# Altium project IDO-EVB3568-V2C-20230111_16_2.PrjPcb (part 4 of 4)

## Sheet P20.SchDoc
size 297 x 209 mm
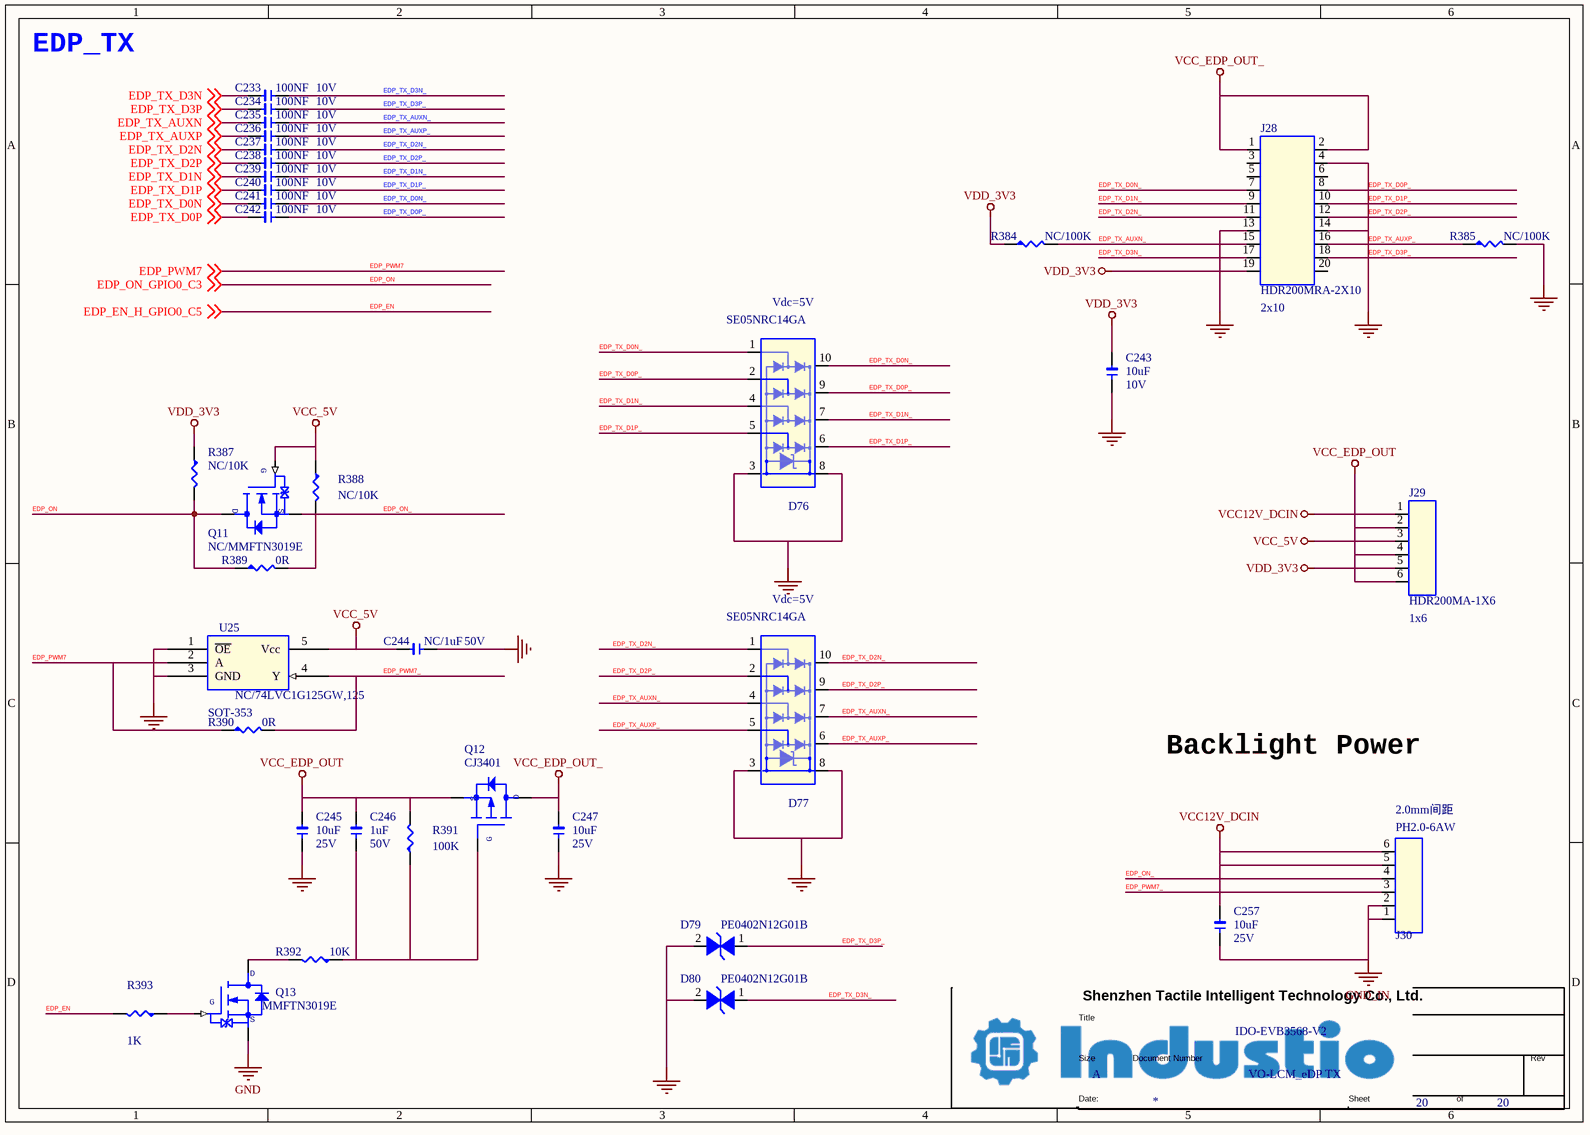
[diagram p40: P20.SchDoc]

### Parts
(Parts that share a designator on the sheet are numbered #1, #2 ... from top to bottom, then left to right.)
*#19  Doc: VO-LCM_eDP TX  Title: IDO-EVB3568-V2  Page Size: A  Page Number: 20  (hidden comment: TitleBlock1)  (graphical)
C233  100NF  DSC2: 10V  [1206]
C234  100NF  DSC2: 10V  [1206]
C235  100NF  DSC2: 10V  [1206]
C236  100NF  DSC2: 10V  [1206]
C237  100NF  DSC2: 10V  [1206]
C238  100NF  DSC2: 10V  [1206]
C239  100NF  DSC2: 10V  [1206]
C240  100NF  DSC2: 10V  [1206]
C241  100NF  DSC2: 10V  [1206]
C242  100NF  DSC2: 10V  [1206]
C243  10uF  DSC2: 10V  [1206]
C244  NC/1uF  DSC2: 50V  [1206]
C245  10uF  DSC2: 25V  [1206]
C246  1uF  DSC2: 50V  [1206]
C247  10uF  DSC2: 25V  [1206]
C257  10uF  DSC2: 25V  [1206]
D76  SE05NRC14GA  DSC2: Vdc=5V  [DFN2510-10L]
D77  SE05NRC14GA  DSC2: Vdc=5V  [DFN2510-10L]
D79  PE0402N12G01B  [V0402]
D80  PE0402N12G01B  [V0402]
J28  HDR200MRA-2X10  DSC2: 2x10  [HDR200MRA-2X10]
J29  HDR200MA-1X6  DSC2: 1x6  [HDR200MA-1X6]
J30  PH2.0-6AW  DSC2: 2.0mm间距  [PH200-6AW]
Q11  NC/MMFTN3019E  [SOT523]
Q12  CJ3401  [SOT23]
Q13  MMFTN3019E  [SOT523]
R384  NC/100K  [R0402]
R385  NC/100K  [R0402]
R387  NC/10K  [R0402]
R388  NC/10K  [R0402]
R389  0R  [R0402]
R390  0R  [R0402]
R391  100K  [R0402]
R392  10K  [R0402]
R393  1K  [R0402]
U25  NC/74LVC1G125GW,125  DSC2: SOT-353  [SOT353]

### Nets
EDP_TX_AUXP_: C234.1 C236.1 C238.1 C240.1 C242.1 C243.1 C244.1 C245.1 C247.1 D76.2 D76.3 D76.5 D76.6 D76.8 D76.9 D77.2 D77.3 D77.5 D77.6 D77.8 D77.9 D79.1(I/O2) D79.2(I/O1) D80.2(I/O1) J28.4 J28.8 J28.10 J28.12 J28.13 J28.14 J28.16 J28.18 Q13.2(SOURCE) R385.1 R385.2 U25.1(~{OE}) U25.3(GND)  [also labelled EDP_TX_D0P_, EDP_TX_D1P_, EDP_TX_D2P_, EDP_TX_D3P_, GND]
GND_IN: C257.1 J30.1 J30.2
VCC12V_DCIN: C257.2 J29.1 J30.5 J30.6
VCC_5V: C244.2 J29.3 Q11.1(GATE) R388.1 U25.5(Vcc)
VCC_EDP_OUT: C245.2 C246.2 J29.2 J29.4 J29.6 Q12.2(SOURCE) R391.2
VCC_EDP_OUT_: C247.2 J28.1 J28.2 Q12.3(DRAIN)
VDD_3V3: C243.2 J28.19 J29.5 R384.1 R387.1
EDP_EN: R393.2 ; off-sheet EDP_EN_H_GPIO0_C5  [also labelled EDP_EN_H_GPIO0_C5]
EDP_ON: Q11.3(DRAIN) R387.2 R389.1 ; off-sheet EDP_ON_GPIO0_C3  [also labelled EDP_ON_GPIO0_C3]
EDP_ON_: J30.4 Q11.2(SOURCE) R388.2 R389.2
EDP_PWM7: R390.1 U25.2(A) ; off-sheet EDP_PWM7
EDP_PWM7_: J30.3 R390.2 U25.4(Y)
EDP_TX_AUXN: C235.2 ; off-sheet EDP_TX_AUXN
EDP_TX_AUXN_: C235.1 D77.4 D77.7 J28.15 R384.2
EDP_TX_AUXP: C236.2 ; off-sheet EDP_TX_AUXP
EDP_TX_D0N: C241.2 ; off-sheet EDP_TX_D0N
EDP_TX_D0N_: C241.1 D76.1 D76.10 J28.7
EDP_TX_D0P: C242.2 ; off-sheet EDP_TX_D0P
EDP_TX_D1N: C239.2 ; off-sheet EDP_TX_D1N
EDP_TX_D1N_: C239.1 D76.4 D76.7 J28.9
EDP_TX_D1P: C240.2 ; off-sheet EDP_TX_D1P
EDP_TX_D2N: C237.2 ; off-sheet EDP_TX_D2N
EDP_TX_D2N_: C237.1 D77.1 D77.10 J28.11
EDP_TX_D2P: C238.2 ; off-sheet EDP_TX_D2P
EDP_TX_D3N: C233.2 ; off-sheet EDP_TX_D3N
EDP_TX_D3N_: C233.1 D80.1(I/O2) J28.17
EDP_TX_D3P: C234.2 ; off-sheet EDP_TX_D3P
NetC246_1: C246.1 Q12.1(GATE) R391.1 R392.1
NetQ13_1: Q13.1(GATE) R393.1
NetQ13_3: Q13.3(DRAIN) R392.2

Not connected (* = marked no-connect by the designer): J28 3 5 6 20

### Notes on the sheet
- EDP_TX
- Backlight Power

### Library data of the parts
C233 C234 = C-0402_Dup2: Manufacture: 三星¦国巨¦村田; Part Name: 贴片电容; Part Number: C020102120060; PCB Footprint: C0402; ID: 60; DSC3: X7R; DSC1: ±10%
C235-C242 = C-0402_Dup2: Part Number: C020102120060; Part Name: 贴片电容; Manufacture: 三星¦国巨¦村田; PCB Footprint: C0402; DSC1: ±10%; DSC3: X7R; ID: 60
C243 = C-0603_Dup2: Part Number: C020102120071; Part Name: 贴片电容; Manufacture: 三星¦国巨¦村田; ERP Number: 1010200076; DSC1: ±20%; DSC3: X5R; ID: 71; PCB Footprint: C0603
C244 = C-0603_Dup2: Manufacture: 三星¦国巨¦村田; Part Name: 贴片电容; Part Number: C020102120069; PCB Footprint: C0603; ID: 69; DSC3: X5R; DSC1: ±10%; ERP Number: 1010200142
C245 = C-0805_Dup1: Manufacture: 三星¦国巨¦村田; Part Name: 贴片电容; Part Number: C020102120074; ID: 74; DSC3: X5R; DSC1: ±10%; ERP Number: 1010200144; PCB Footprint: C0805
C246 = C-0603_Dup2: Part Number: C020102120069; Part Name: 贴片电容; Manufacture: 三星¦国巨¦村田; ERP Number: 1010200142; DSC1: ±10%; DSC3: X5R; ID: 69; PCB Footprint: C0603
C247 = C-0805_Dup1: Part Number: C020102120074; Part Name: 贴片电容; Manufacture: 三星¦国巨¦村田; ERP Number: 1010200144; DSC1: ±10%; DSC3: X5R; ID: 74; PCB Footprint: C0805
C257 = C-0805_Dup1: Part Number: C020102120074; Part Name: 贴片电容; Manufacture: 三星¦国巨¦村田; PCB Footprint: C0805; ERP Number: 1010200144; DSC1: ±10%; DSC3: X5R; ID: 74
D76 = DI-ESD-SE05NRC14GA: Manufacture: 硕凯; Part Number: C040504013981; Part Name: ESD; Solder: 推荐; ID: 8; DSC5: Cj=0.4pF; DSC4: Vc=20V; DSC3: Vbr=8V; DSC1: 双向
D77 = DI-ESD-SE05NRC14GA: Part Name: ESD; Part Number: C040504013981; Manufacture: 硕凯; DSC1: 双向; DSC3: Vbr=8V; DSC4: Vc=20V; DSC5: Cj=0.4pF; ID: 8; Solder: 推荐
D79 = DI-ESD: ESD 0402; Manufacturer: INPAQ; Manufacture P/N: MLVG04021R0UV18; Part Number: C040504013980; Manufacture: 硕凯; PN Type: Varistor; DSC1: 双向; DSC2: Vdc=12V; DSC4: Vc=40V; DSC5: Cj=0.05pF; ID: 1; Solder: 推荐
D80 = DI-ESD: ESD 0402; Manufacturer: INPAQ; Manufacture P/N: MLVG04021R0UV18; Part Number: C040504013980; Manufacture: 硕凯; PN Type: Varistor; Solder: 推荐; ID: 1; DSC5: Cj=0.05pF; DSC4: Vc=40V; DSC2: Vdc=12V; DSC1: 双向
J28 = J-HDR-D-20: Part Name: 双排针; Part Number: J010102760085; ID: 29; DSC7: X4621WR-2x10I-C28D40（星坤）; DSC6: 黑胶; DSC5: 2.8+2(H塑高)+4 mm; DSC4: 通孔弯针; DSC3: 2mm脚距; DSC1: 双排单塑
J29 = J-HDR-6: Part Name: 单排针; Part Number: J010206123880; ID: 66; DSC7: X4611WV-06I-C28D40（星坤）; DSC6: 黑胶; DSC5: 针长8.8mm  2.8+2(H塑高)+4 mm; DSC4: 通孔直针; DSC3: 2mm脚距; DSC1: 单排单塑
J30 = J-H-6P: Part Name: PH; Part Number: J020302820024; ID: 20; DSC6: X2016WR-06-46SN(星坤); DSC5: JLX-PH20-6B（九龙熹）; DSC4: 米黄色胶壳 耐高温; DSC3: 通孔90度弯针; DSC1: 6p
Q11 = N-MOS-Q_Dup1: Part Number: C030202190004; Part Name: N-MOS; Manufacture: 先科; ERP Number: 1010800011; DSC1: Vds=30V; DSC2: Id=100mA; DSC3: Vgs(th)=1.5V; DSC4: Vgs=±20V; DSC5: pd=150mW; ID: 4
Q12 = P-MOS: Manufacture: 长电; Part Number: C030202190001; ID: 1; DSC5: pd=350mW; DSC4: Vgs=±12V; DSC3: Vgs(th)=1.3V; DSC2: Id=-4.2A; DSC1: Vds=-30V; ERP Number: 1010800001
Q13 = N-MOS-Q_Dup1: Manufacture: 先科; Part Name: N-MOS; Part Number: C030202190004; DSC5: pd=150mW; DSC4: Vgs=±20V; DSC3: Vgs(th)=1.5V; DSC2: Id=100mA; DSC1: Vds=30V; ERP Number: 1010800011
R384 = R-0402_Dup4: Part Number: C011002080353; Part Name: 贴片电阻; ID: 353; DSC2: 1/16W; DSC1: ±5%; ERP Number: 1010200103
R385 R391 = R-0402_Dup4: Part Name: 贴片电阻; Part Number: C011002080353; ERP Number: 1010200103; DSC1: ±5%; DSC2: 1/16W; ID: 353
R387 R388 = R-0402_Dup4: Part Name: 贴片电阻; Part Number: C011002080328; ERP Number: 1010200096; DSC1: ±5%; DSC2: 1/16W; ID: 328
R389 R390 = R-0402_Dup4: Part Name: 贴片电阻; Part Number: C011002080217; ERP Number: 1010200100; DSC1: ±5%; DSC2: 1/16W; ID: 217
R392 = R-0402_Dup4: Part Number: C011002080328; Part Name: 贴片电阻; ID: 328; DSC2: 1/16W; DSC1: ±5%; ERP Number: 1010200096
R393 = R-0402_Dup4: Part Name: 贴片电阻; Part Number: C011002080303; ERP Number: 1010200104; DSC1: ±5%; DSC2: 1/16W; ID: 303
U25 = U-74LVC1G125GW-125: Manufacture: Nexperia(安世); Part Number: C080302460001; Part Name: 逻辑缓冲器; ID: 5; DSC3: -55℃~+125℃; DSC1: 1位 高速缓冲 三态输出 VCC=1.65V-5.5V; ERP Number: 1010100128

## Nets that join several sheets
EDP_TX_AUXP_: P04 (31 pins), P05 (32 pins), P06 (17 pins), P07 (116 pins), P08 (30 pins), P09 (31 pins), P10 (40 pins), P11 (55 pins), P12 (54 pins), P13 (24 pins), P14 (41 pins), P15 (43 pins), P16 (8 pins), P17 (17 pins), P18 (47 pins), P19 (27 pins), P20 (37 pins)
GND_EARTH: P04 (Hole1.1 Hole2.1 Hole3.1 Hole4.1), P14 (J22.SH1 J22.SH2), P15 (C261.2 J23.SH1 J23.SH2 R419.2)
GND_IN: P04 (8 pins), P11 (C256.1 J18.1 J18.2), P20 (C257.1 J30.1 J30.2)
I2C_SCL_RTC: P13 (R206.1), P17 (9 pins)
VCC3V3_SD: P05 (J2.210), P06 (C31.2 D2.2 J3.4)
VCC5V_SYS: P04 (7 pins), P05 (R17.1), P10 (D42.A D43.A Q5.1)
VCC12V_DCIN: P04 (F2.1 J1.4 J32.3 J32.4), P11 (C256.2 J17.1 J18.5 J18.6), P20 (C257.2 J29.1 J30.5 J30.6)
VCC_1V8: P05 (J2.237), P07 (R30.2), P09 (R413.1), P11 (R408.1), P12 (R154.2 R155.2), P13 (R200.1), P14 (R250.1), P15 (R298.1), P16 (Q19.1 R398.1 R399.1)
VCC_3V3: P04 (R14.1), P05 (J2.245)
VCC_5V: P04 (9 pins), P07 (12 pins), P08 (C248.2 R86.1), P09 (C82.2 C83.2 L15.1 U12.6), P11 (9 pins), P16 (C177.1 J24.35 J24.36), P18 (C205.2 C206.2 U22.4), P20 (5 pins)
VDD_3V3: P04 (6 pins), P07 (R37.2 R74.2 R76.1), P08 (R80.1 R85.1), P09 (7 pins), P10 (5 pins), P11 (10 pins), P12 (6 pins), P13 (5 pins), P14 (R258.1), P15 (R267.2 R306.1), P16 (R400.1 R401.1), P17 (D69.A R326.2 R327.2), P19 (R359.1), P20 (5 pins)
4G_5G_RESET: P05 (J2.9), P18 (R337.2)
4G_PWREN_H_GPIO0_D5: P05 (J2.11), P18 (R344.1)
BT_REG_ON_H_GPIO1_D4: P05 (J2.18), P13 (R209.1)
BT_WAKE_HOST_H_GPIO2_C1: P05 (J2.228), P13 (R199.1)
CAM0_PDN_H_GPIO1_D0: P05 (J2.10), P12 (R150.1)
CAM0_RST_L__GPIO1_D1: P05 (J2.12), P12 (R151.1)
CAM1_PDN_H_GPIO1_D2: P05 (J2.14), P12 (R164.1)
CAM1_RST_L_GPIO1_C7: P05 (J2.16), P12 (R165.1)
CAM_CLKOUT0: P05 (J2.108), P12 (R163.1)
CAMERA_PWREN_GPIO4_D2: P05 (J2.13), P12 (R416.1)
CAN1_RX_M0: P05 (J2.154), P16 (R310.4)
CAN1_TX_M0: P05 (J2.156), P16 (R310.3)
CAN2_RX_M0: P05 (J2.44), P16 (D90.A R398.2)
CAN2_TX_M0: P05 (J2.46), P16 (Q19.2 R399.2)
CIF_CLKOUT_SOC: P05 (J2.52), P12 (R149.1)
CLK_32K_OUT_GPIO0_B0: P05 (J2.112), P19 (R352.1)
EDP_EN: P05 (J2.130), P20 (R393.2)
EDP_ON: P05 (J2.126), P20 (Q11.3 R387.2 R389.1)
EDP_PWM7: P05 (J2.132), P20 (R390.1 U25.2)
EDP_TX_AUXN: P05 (J2.197), P20 (C235.2)
EDP_TX_AUXP: P05 (J2.199), P20 (C236.2)
EDP_TX_D0N: P05 (J2.213), P20 (C241.2)
EDP_TX_D0P: P05 (J2.215), P20 (C242.2)
EDP_TX_D1N: P05 (J2.209), P20 (C239.2)
EDP_TX_D1P: P05 (J2.211), P20 (C240.2)
EDP_TX_D2N: P05 (J2.205), P20 (C237.2)
EDP_TX_D2P: P05 (J2.207), P20 (C238.2)
EDP_TX_D3N: P05 (J2.201), P20 (C233.2)
EDP_TX_D3P: P05 (J2.203), P20 (C234.2)
EXT_EN: P04 (R13.1), P05 (J2.249)
FE1_1_DM1: P07 (L8.2 R52.1 U8.23), P16 (R307.1)
FE1_1_DM4: P07 (U8.14), P18 (R340.2)
FE1_1_DP1: P07 (L8.1 R56.1 U8.24), P16 (R308.1)
FE1_1_DP4: P07 (U8.15), P18 (R341.2)
GMAC0_MCLKINOUT: P05 (J2.230), P14 (C131.2 R216.1 R219.2)
GMAC0_MDC: P05 (J2.232), P14 (U19.13)
GMAC0_MDIO: P05 (J2.234), P14 (R249.1 U19.14)
GMAC0_RSTn_GPIO2_D5: P05 (J2.77), P14 (R248.1)
GMAC0_RXCLK: P05 (J2.223), P14 (C147.2 R256.2)
GMAC0_RXD0: P05 (J2.222), P14 (R252.2)
GMAC0_RXD1: P05 (J2.224), P14 (R253.2)
GMAC0_RXD2: P05 (J2.219), P14 (R254.2)
GMAC0_RXD3: P05 (J2.221), P14 (R255.2)
GMAC0_RXDV_CRS: P05 (J2.226), P14 (R257.2)
GMAC0_TXCLK: P05 (J2.229), P14 (C134.2 R234.1)
GMAC0_TXD0: P05 (J2.216), P14 (R224.1)
GMAC0_TXD1: P05 (J2.218), P14 (R227.1)
GMAC0_TXD2: P05 (J2.225), P14 (R228.1)
GMAC0_TXD3: P05 (J2.227), P14 (R231.1)
GMAC0_TXEN: P05 (J2.220), P14 (R232.1)
GMAC1_MCLKINOUT_M1: P05 (J2.54), P15 (C155.2 R270.1 R271.2)
GMAC1_MDC_M1: P05 (J2.48), P15 (U20.13)
GMAC1_MDIO_M1: P05 (J2.50), P15 (R297.1 U20.14)
GMAC1_RSTn_GPIO2_D7: P05 (J2.73), P15 (R296.1)
GMAC1_RXCLK_M1: P05 (J2.45), P15 (C171.2 R304.2)
GMAC1_RXD0_M1: P05 (J2.34), P15 (R300.2)
GMAC1_RXD1_M1: P05 (J2.36), P15 (R301.2)
GMAC1_RXD2_M1: P05 (J2.41), P15 (R302.2)
GMAC1_RXD3_M1: P05 (J2.43), P15 (R303.2)
GMAC1_RXDV_CRS_M1: P05 (J2.38), P15 (R305.2)
GMAC1_TXCLK_M1: P05 (J2.39), P15 (C158.2 R282.1)
GMAC1_TXD0_M1: P05 (J2.47), P15 (R272.1)
GMAC1_TXD1_M1: P05 (J2.49), P15 (R275.1)
GMAC1_TXD2_M1: P05 (J2.35), P15 (R276.1)
GMAC1_TXD3_M1: P05 (J2.37), P15 (R279.1)
GMAC1_TXEN_M1: P05 (J2.32), P15 (R280.1)
HDMI_TX_CLKN: P05 (J2.147), P10 (L19.2)
HDMI_TX_CLKP: P05 (J2.149), P10 (L19.1)
HDMI_TX_D0N: P05 (J2.155), P10 (L18.2)
HDMI_TX_D0P: P05 (J2.153), P10 (L18.1)
HDMI_TX_D1N: P05 (J2.159), P10 (L17.2)
HDMI_TX_D1P: P05 (J2.157), P10 (L17.1)
HDMI_TX_D2N: P05 (J2.163), P10 (L16.2)
HDMI_TX_D2P: P05 (J2.161), P10 (L16.1)
HDMI_TX_HPDIN: P05 (J2.143), P10 (R107.1)
HDMITX_CEC_M0: P05 (J2.89), P10 (Q5.2 R109.1)
HOST_WAKE_BT_H_GPIO1_D3: P05 (J2.20), P13 (R394.1)
HP_SNS: P05 (J2.244), P08 (J10.1 R81.1)
HPL_OUT: P05 (J2.242), P08 (C72.2 R84.1)
HPR_OUT: P05 (J2.246), P08 (C75.2 R82.1)
HUB_RST_: P05 (J2.8), P07 (R53.1)
I2C1_SCL: P05 (J2.146), P16 (R311.2)
I2C1_SDA: P05 (J2.148), P16 (R311.1)
I2C2_SCL_M0: P05 (J2.150), P11 (R111.1 R115.1)
I2C2_SDA_M0: P05 (J2.152), P11 (R112.1 R116.1)
I2C3_SCL_M1: P05 (J2.74), P09 (R92.1 R96.1)
I2C3_SDA_M1: P05 (J2.72), P09 (R93.1 R97.1)
I2C4_SCL_M0: P05 (J2.42), P12 (R152.1 R155.1)
I2C4_SDA_M0: P05 (J2.40), P12 (R153.1 R154.1)
I2C5_SCL-HDMI: P05 (J2.93), P10 (Q3.2 R103.2)
I2C5_SCL_M0: P05 (J2.78), P12 (Q17.3), P17 (R327.1 R328.2)
I2C5_SDA-HDMI: P05 (J2.91), P10 (Q4.2 R105.2)
I2C5_SDA_M0: P05 (J2.76), P12 (Q16.3), P17 (R326.1 R329.2)
LVDS_EN: P05 (J2.65), P11 (R137.2)
LVDS_ON: P05 (J2.67), P11 (Q7.3 R132.2 R135.1)
MIC1_INN: P05 (J2.250), P08 (C66.2 D97.2)
MIC1_INP: P05 (J2.248), P08 (C64.2)
MIPI_CSI_RX_CLK0N: P05 (J2.103), P12 (R148.1)
MIPI_CSI_RX_CLK0P: P05 (J2.101), P12 (R147.1)
MIPI_CSI_RX_CLK1N: P05 (J2.99), P12 (R158.1)
MIPI_CSI_RX_CLK1P: P05 (J2.97), P12 (R157.1)
MIPI_CSI_RX_D0N: P05 (J2.119), P12 (R139.1)
MIPI_CSI_RX_D0P: P05 (J2.117), P12 (R139.2)
MIPI_CSI_RX_D1N: P05 (J2.115), P12 (R139.3)
MIPI_CSI_RX_D1P: P05 (J2.113), P12 (R139.4)
MIPI_CSI_RX_D2N: P05 (J2.111), P12 (R140.1 R141.4)
MIPI_CSI_RX_D2P: P05 (J2.109), P12 (R140.2 R141.3)
MIPI_CSI_RX_D3N: P05 (J2.107), P12 (R140.3 R141.2)
MIPI_CSI_RX_D3P: P05 (J2.105), P12 (R140.4 R141.1)
MIPI_DSI_TX0_CLKN: P05 (J2.133), P11 (D51.2 D51.9 J15.27 R127.1)
MIPI_DSI_TX0_CLKP: P05 (J2.131), P11 (D51.1 D51.10 J15.26 R126.1)
MIPI_DSI_TX0_D0N: P05 (J2.141), P11 (D53.1 J15.33 R122.1)
MIPI_DSI_TX0_D0P: P05 (J2.139), P11 (D52.1 J15.32 R122.2)
MIPI_DSI_TX0_D1N: P05 (J2.137), P11 (D51.5 D51.6 J15.30 R122.3)
MIPI_DSI_TX0_D1P: P05 (J2.135), P11 (D51.4 D51.7 J15.29 R122.4)
MIPI_DSI_TX0_D2N: P05 (J2.129), P11 (D49.5 D49.6 J15.24 R123.1)
MIPI_DSI_TX0_D2P: P05 (J2.127), P11 (D49.4 D49.7 J15.23 R123.2)
MIPI_DSI_TX0_D3N: P05 (J2.125), P11 (D49.2 D49.9 J15.21 R123.3)
MIPI_DSI_TX0_D3P: P05 (J2.123), P11 (D49.1 D49.10 J15.20 R123.4)
MIPI_DSI_TX0_RST_GPIO4_C3: P05 (J2.136), P11 (R417.1)
MIPI_DSI_TX1_CLKN: P05 (J2.96), P09 (D37.2 D37.9 J13.27)
MIPI_DSI_TX1_CLKP: P05 (J2.94), P09 (D37.1 D37.10 J13.26)
MIPI_DSI_TX1_D0N: P05 (J2.104), P09 (D38.1 J13.33)
MIPI_DSI_TX1_D0P: P05 (J2.102), P09 (D36.1 J13.32)
MIPI_DSI_TX1_D1N: P05 (J2.100), P09 (D37.5 D37.6 J13.30)
MIPI_DSI_TX1_D1P: P05 (J2.98), P09 (D37.4 D37.7 J13.29)
MIPI_DSI_TX1_D2N: P05 (J2.92), P09 (D35.5 D35.6 J13.24)
MIPI_DSI_TX1_D2P: P05 (J2.90), P09 (D35.4 D35.7 J13.23)
MIPI_DSI_TX1_D3N: P05 (J2.88), P09 (D35.2 D35.9 J13.21)
MIPI_DSI_TX1_D3P: P05 (J2.86), P09 (D35.1 D35.10 J13.20)
MIPI_TX1_BL_PWM12_M0: P05 (J2.70), P09 (R91.1)
MIPI_TX1_RST_GPIO2_D6: P05 (J2.75), P09 (R418.1)
NTC_SARADC_VIN3: P05 (J2.5), P16 (R312.2)
PCIE20_CLKREQn_M2_3V3_L: P05 (J2.2), P19 (R348.1)
PCIE20_PERSTn_M2_3V3_L: P05 (J2.6), P19 (R347.1)
PCIE20_PRSNT_3V3_L_GPIO3_A6: P05 (J2.57), P19 (R382.2)
PCIE20_REFCLKN: P05 (J2.184), P19 (R360.1)
PCIE20_REFCLKP: P05 (J2.182), P19 (R361.1)
PCIE20_RXN: P05 (J2.188), P19 (R355.1)
PCIE20_RXP: P05 (J2.186), P19 (R356.1)
PCIE20_TXN: P05 (J2.192), P19 (C212.1)
PCIE20_TXP: P05 (J2.190), P19 (C213.1)
PCIE20_WAKEn_M2_3V3_L: P05 (J2.4), P19 (R349.1)
PWM3_IR: P05 (J2.124), P16 (R311.3)
PWM13_M1: P05 (J2.144), P11 (R110.1)
RK809-CLK32K: P05 (J2.247), P13 (R205.1)
RK809_PWRON: P05 (J2.251), P16 (R314.1), P17 (C259.2 R412.1)
RK809_VDC: P04 (R7.1 R9.2), P05 (J2.252)
SARADC_VIN0_KEY/RECOVERY: P05 (J2.1), P16 (R312.1), P17 (C182.2 R330.1)
SARADC_VIN2_HP_HOOK: P05 (J2.3), P16 (R312.3)
SARADC_VIN4: P05 (J2.7), P16 (R312.4)
SDMMC0_CLK: P05 (J2.206), P06 (R21.1)
SDMMC0_CMD: P05 (J2.204), P06 (R20.1)
SDMMC0_D0: P05 (J2.196), P06 (R22.1)
SDMMC0_D1: P05 (J2.198), P06 (R23.1)
SDMMC0_D2: P05 (J2.200), P06 (R18.1)
SDMMC0_D3: P05 (J2.202), P06 (R19.1)
SDMMC0_DET_L: P05 (J2.208), P06 (R24.1)
SDMMC2_CLK_M0: P05 (J2.27), P13 (R187.1)
SDMMC2_CMD_M0: P05 (J2.25), P13 (R185.2 R186.1)
SDMMC2_D0_M0: P05 (J2.17), P13 (R180.2 R181.1)
SDMMC2_D1_M0: P05 (J2.19), P13 (R182.1)
SDMMC2_D2_M0: P05 (J2.21), P13 (R183.1)
SDMMC2_D3_M0: P05 (J2.23), P13 (R184.1)
SPI0_CLK_M1: P05 (J2.81), P16 (R315.3)
SPI0_CS0_M1: P05 (J2.83), P16 (R315.4)
SPI0_MISO_M1: P05 (J2.87), P16 (R315.2)
SPI0_MOSI_M1: P05 (J2.85), P16 (R315.1)
SPK_CTL_H_GPIO3_B0: P05 (J2.53), P08 (R89.1)
SPK_MUTE_H_GPIO3_A7: P05 (J2.55), P08 (R90.1)
SYS_LED_GPIO4_C5: P04 (R8.1), P05 (J2.142)
SYS_RESETn: P05 (J2.235), P16 (R311.4)
TP0_INT_L_GPIO3_A3: P05 (J2.63), P11 (R114.1)
TP0_RST_L_GPIO3_A4: P05 (J2.61), P11 (R113.1)
TP1_INT_L_GPIO3_C0: P05 (J2.68), P09 (R95.1)
TP1_RST_L_GPIO3_C1: P05 (J2.66), P09 (R94.1)
UART0_CTSn: P05 (J2.134), P16 (R310.2)
UART0_RTSn: P05 (J2.128), P16 (R310.1)
UART0_RX: P05 (J2.120), P16 (R309.3)
UART0_TX: P05 (J2.122), P16 (R309.4)
UART2_RX_M0: P05 (J2.116), P06 (R25.1)
UART2_TX_M0: P05 (J2.118), P06 (R26.1)
UART4_RX_M1: P05 (J2.82), P16 (R309.2)
UART4_TX_M1: P05 (J2.80), P16 (R309.1)
UART5_RX_M1: P05 (J2.62), P16 (R316.3)
UART5_TX_M1: P05 (J2.64), P16 (R316.4)
UART7_RX_M1: P05 (J2.58), P16 (R316.1)
UART7_TX_M1: P05 (J2.60), P16 (R316.2)
UART8_CTSn_M0: P05 (J2.233), P13 (R201.1 U18.41)
UART8_RTSn_M0: P05 (J2.231), P13 (U18.44)
UART8_RX_M0: P05 (J2.238), P13 (U18.42)
UART8_TX_M0: P05 (J2.236), P13 (U18.43)
USB1_PWREN_H_GPIO3_A5: P05 (J2.59), P07 (R57.1)
USB2_HOST2_DM: P05 (J2.28), P07 (L6.2 R42.1)
USB2_HOST2_DP: P05 (J2.26), P07 (L6.1 R43.1)
USB2_HOST2_PWREN_H_GPIO0_A6: P05 (J2.110), P07 (U5.4)
USB2_HOST3_DM: P05 (J2.24), P07 (R71.2)
USB2_HOST3_DP: P05 (J2.22), P07 (R69.2)
USB2_PWREN_H_GPIO4_C3: P05 (J2.138), P07 (R70.1)
USB3_HOST1_DM: P05 (J2.169), P07 (L7.2 R46.1)
USB3_HOST1_DP: P05 (J2.167), P07 (L7.1 R47.1)
USB3_HOST1_PWREN_H_GPIO3_A0: P05 (J2.71), P07 (U6.4)
USB3_HOST1_SSRXN: P05 (J2.175), P07 (R375.1), P18 (R423.1)
USB3_HOST1_SSRXP: P05 (J2.177), P07 (R376.1), P18 (R422.1)
USB3_HOST1_SSTXN: P05 (J2.171), P07 (C290.1), P18 (C187.1)
USB3_HOST1_SSTXP: P05 (J2.173), P07 (C291.1), P18 (C189.1)
USB3_OTG0_DM: P05 (J2.189), P07 (L5.2 R29.1)
USB3_OTG0_DP: P05 (J2.187), P07 (L5.1 R34.1)
USB3_OTG0_ID: P05 (J2.193), P07 (Q1.3 R31.2)
USB3_OTG0_SSRXN: P05 (J2.183), P07 (R48.1)
USB3_OTG0_SSRXP: P05 (J2.185), P07 (R49.1)
USB3_OTG0_SSTXN: P05 (J2.179), P07 (C39.1)
USB3_OTG0_SSTXP: P05 (J2.181), P07 (C41.1)
USB3_OTG0_VBUSDET: P05 (J2.191), P07 (R27.2 R28.2)
USB3_PWREN_H_GPIO4_C4: P05 (J2.140), P07 (R77.1)
USB_OTG_PWREN_H_GPIO0_A5: P05 (J2.212), P07 (R32.1)
WIFI_PWREN_L_GPIO0_B7: P05 (J2.114), P13 (R207.2)
WIFI_REG_ON_H_GPIO3_D5: P05 (J2.33), P13 (R196.1 R210.1)
WIFI_WAKE_HOST_H_GPIO3_D4: P05 (J2.29), P13 (U18.13)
